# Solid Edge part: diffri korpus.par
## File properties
Author: Türk
Template: Iso Part.par
Last saved by: Türk
Revision: 25
Application: Solid Edge
Accuracy: 0,990
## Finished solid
Body 1: sheet body, 3 faces, 64 edges, 64 vertices.
  Faces by surface: plane 3
  Edges by curve: line 64
Body 2: solid body, 102 faces, 277 edges, 173 vertices.
  Faces by surface: plane 67, cylinder 35
  Edges by curve: line 180, circle 75, ellipse 16, intersection 6
Bounding box of the edges (mm): 315.000 x 120.000 x 267.500, from (-157.5, 0, -105) to (157.5, 120, 162.5).
Cylindrical faces by radius (mm): R5 x2, R7.5 x4, R20 x4, R25 x4, R27.5 x3, R40 x4, R50 x6, R52.5 x3, R100 x4, R102.5 x1
Planar faces by outward normal: +x 12, +y 4, +z 10, -x 13, -y 8, -z 12, oblique 8
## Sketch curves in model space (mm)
line (-33, 47, 102.5) -> (-33, 39.6989, 102.5)
line (-33, 0, 102.5) -> (-33, 39.6989, 102.5)
line (-87.5, 0, 0) -> (72.7603, 0, 0)
line (87.7603, 0, 0) -> (-157.5, 0, 0)
line (-157.5, 0, 0) -> (-157.5, 0, 102.5)
line (17, 0, 102.5) -> (-33, 0, 102.5)
line (17, 0, 102.5) -> (67, 0, 102.5)
arc centre (137.5, 87.2842, -25) radius 25 from (137.5, 87.2842, -50) through (137.5, 102.4224, -44.8956) to (137.5, 111.3789, -31.6667)
arc centre (137.5, 0, 0) radius 50 from (137.5, 0, 50) through (137.5, 49.978, -1.4817) to (137.5, 0, -50)
arc centre (137.5, 87.2842, 25) radius 25 from (137.5, 111.3789, 31.6667) through (137.5, 102.4224, 44.8956) to (137.5, 87.2842, 50)
line (137.5, 87.2842, 50) -> (137.5, 0, 50)
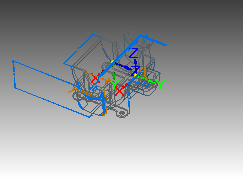
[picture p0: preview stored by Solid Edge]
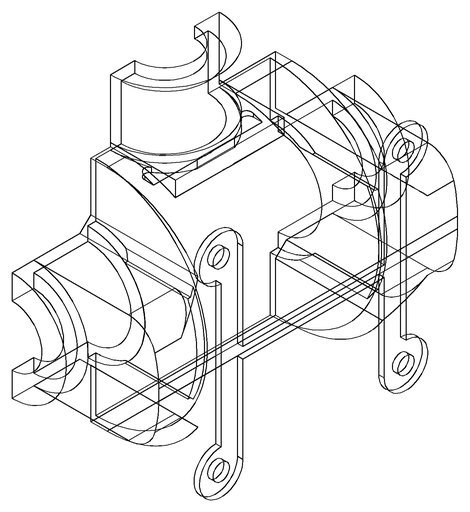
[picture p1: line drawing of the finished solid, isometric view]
